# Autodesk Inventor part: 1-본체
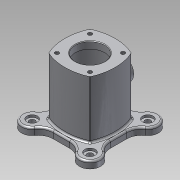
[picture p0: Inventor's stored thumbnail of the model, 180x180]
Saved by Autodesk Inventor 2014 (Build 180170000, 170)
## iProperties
Created: 2016-05
Part Number: 1-본체
Material: 알루미늄 6061
Document SubType Name: Modeling
Designer: S.Y.PARK
Density: 2.71 g/cm^3
Appearance: 알루미늄 - 평지
Author: S.Y.PARK
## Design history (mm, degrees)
sketch "스케치1"
  geometry: L1 (-35.355, -35.355)-(35.355, -35.355); L2 (35.355, -35.355)-(35.355, 35.355); L3 (35.355, 35.355)-(-35.355, 35.355); L4 (-35.355, 35.355)-(-35.355, -35.355); L5 (-35.355, -35.355)-(35.355, 35.355); L6 (35.355, -35.355)-(-35.355, 35.355); A1 r 85.579 centre (0, 42.579) between (-35.355, -35.355) and (35.355, -35.355); A2 r 85.579 centre (0, -42.579) between (35.355, 35.355) and (-35.355, 35.355); A3 r 85.579 centre (42.579, 0) between (-35.355, 35.355) and (-35.355, -35.355); A4 r 85.579 centre (-42.579, 0) between (35.355, -35.355) and (35.355, 35.355); 4 further points
  constraints: 12 end point, 9 point on circle, 4 centre point, 2 equal radius, 2 midpoint, 2 parallel, 2 perpendicular, 1 coincident, 1 horizontal, 1 vertical alignment
  dimensions: "d2" = 100 distance of L1.start L2.end; "d3" = 86 dimension on A2 A1; "d4" = 43 distance of point (0, 0) point (0, -43)
extrude "돌출1" new body sketch "스케치1" distance "d5" = 98; taper "d6" = 0 deg
sketch "스케치2"
  geometry: L1 (49, -49)-(-49, -49); L2 (-49, -49)-(-49, 49); L3 (-49, 49)-(49, 49); L4 (49, 49)-(49, -49); 3 further points
  constraints: 8 end point, 2 midpoint, 2 parallel, 1 horizontal, 1 horizontal alignment, 1 perpendicular, 1 vertical alignment
  dimensions: "d7" = 98 distance of L1.start L1.end; "d8" = 98 distance of L1.end L2.end
extrude "돌출2" join sketch "스케치2" distance "d9" = 12; taper "d10" = 0 deg
sketch "스케치3"
  geometry: L1 (0, 0)-(49.497, -49.497); L2 (0, 0)-(29.49, 0); L3 (0, 0)-(0, -21.208); C1 r 18 at (49.497, -49.497); C2 r 18 at (49.497, 49.497); C3 r 18 at (-49.497, -49.497); C4 r 18 at (-49.497, 49.497); 1 further point
  constraints: 6 end point, 4 centre point, 3 symmetric about line, 2 coincident, 1 horizontal, 1 perpendicular, 3 other
  dimensions: "d12" = 45 deg angle of L2 L1; "d13" = 70 distance of L1.start L1.end; "d14" = 29.49011 distance of L1.start L2.end; "d16" = 18 radius of C1; "d17" = 21.20826 distance of L1.start L3.end
extrude "돌출3" join sketch "스케치3" distance "d18" = 12; taper "d19" = 0 deg
fillet "모깎기1" dims "d20" = 25
node "작업 평면1"
sketch "스케치4"
  geometry: L1 (14.162, -12)-(-14.162, -12) reference; C1 r 20 at (0, 49); 1 further point
  constraints: 1 centre point, 1 vertical alignment
  dimensions: "d22" = 61 distance from line of L1 C1.centre; "d23" = 40 diameter of C1
extrude "돌출4" join sketch "스케치4" stored distance "d24" = 12; taper "d25" = 10 deg
hole "구멍1" diameter "d28" = 25; stored, may be unused: countersink angle "d32" = 90 deg, drill point angle "d34" = 0 deg; dims "d26" = 10, "d27" = 10, "d29" = 6, "d30" = 30, "d31" = 8, "d33" = 8
sketch "스케치5"
  geometry: 2 further points
  constraints: 1 coincident
hole "구멍2" sketch "스케치5" at (0, 0) diameter "d35" = 50; stored, may be unused: countersink angle "d39" = 90 deg, drill point angle "d41" = 0 deg; dims "d36" = 6, "d37" = 30, "d38" = 8, "d40" = 12
hole "구멍3" diameter "d44" = 70; stored, may be unused: countersink angle "d48" = 90 deg, drill point angle "d50" = 0 deg; dims "d42" = 10, "d43" = 10, "d45" = 6, "d46" = 30, "d47" = 8, "d49" = 86
hole "구멍4" diameter "d53" = 50; stored, may be unused: countersink angle "d57" = 90 deg, drill point angle "d59" = 0 deg; dims "d51" = 10, "d52" = 10, "d54" = 6, "d55" = 30, "d56" = 8, "d58" = 12
sketch "스케치6"
  geometry: L1 (0, 0)-(-13.472, 0); L2 (0, 0)-(-28.284, 28.284)
  constraints: 4 end point, 1 horizontal
  dimensions: "d60" = 40 distance of L1.start L2.end; "d61" = 45 deg angle of L2 L1; "d62" = 13.47211 distance of L1.start L1.end
hole "구멍5" sketch "스케치6" at (-28.284, 28.284) diameter "d63" = 6.647; stored, may be unused: countersink angle "d67" = 90 deg, drill point angle "d69" = 118 deg; dims "d64" = 7, "d65" = 30, "d66" = 8, "d68" = 10
node "작업 평면2"
hole "구멍6" diameter "d75" = 10; stored, may be unused: countersink angle "d79" = 90 deg, drill point angle "d81" = 0 deg; dims "d73" = 10, "d74" = 10, "d76" = 7, "d77" = 18, "d78" = 4, "d80" = 10
fillet "모깎기2" dims "d85" = 3
chamfer "모따기1" distance "d86" = 1; stored, may be unused: second distance "d87" = 2, angle "d88" = 45 deg
fillet "모깎기3" dims "d89" = 3
fillet "모깎기4" dims "d90" = 3
chamfer "모따기2" distance "d91" = 1; stored, may be unused: second distance "d92" = 2, angle "d93" = 45 deg
fillet "모깎기5" dims "d94" = 3
fillet "모깎기6" dims "d95" = 3
fillet "모깎기7" dims "d96" = 3
node "솔리드1"
pattern_circular "원형 패턴1" dims angle "d71" = 360 deg
mirror "대칭1"
pattern_circular "원형 패턴2" dims angle "d83" = 360 deg
other parameters: "d21" = 55
